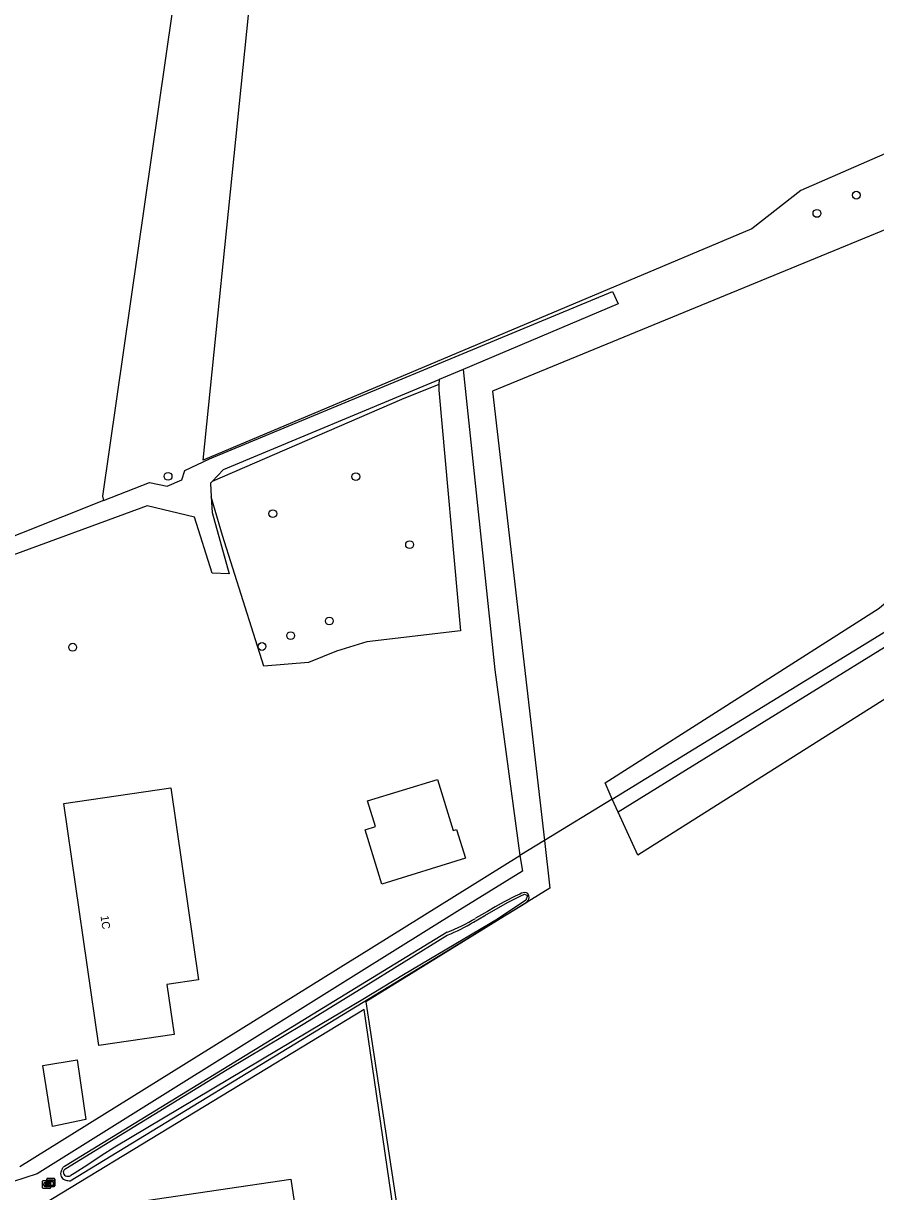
# Model space of a CAD drawing. Extents: x 162722 to 165099, y 384721 to 386283.
# Drawn here: x 164178.9 to 164285.4, y 385084.3 to 385230.3 of the extents above; entities that cross this region are included whole.
import ezdxf

# ---------------------------------------------------------------- set-up
doc = ezdxf.new("R2010")
doc.units = 0
for name, color, linetype in [('IMGEO_Boom', 7, 'Continuous'), ('IMGEO_Grasland_agrarisch', 7, 'Continuous'), ('IMGEO_Grasland_overig', 7, 'Continuous'), ('IMGEO_Groenvoorziening', 7, 'Continuous'), ('IMGEO_Kast', 7, 'Continuous'), ('IMGEO_Loofbos', 7, 'Continuous'), ('IMGEO_Pand', 7, 'Continuous'), ('IMGEO_Pand_nummerreeks', 7, 'Continuous'), ('IMGEO_Rioolput', 7, 'Continuous'), ('IMGEO_Waterloop', 7, 'Continuous')]:
    doc.layers.add(name, color=color, linetype=linetype)

msp = doc.modelspace()

# ---------------------------------------------------------------- linework, layer by layer
at = {"layer": 'IMGEO_Boom'}
for centre in [(164282.97, 385208.81), (164278.05, 385206.53), (164197, 385173.67), (164220.46, 385173.63), (164210.08, 385169.01), (164227.17, 385165.13), (164217.14, 385155.59), (164208.74, 385152.41), (164212.32, 385153.76), (164185.08, 385152.31)]:
    msp.add_circle(centre, 0.489, dxfattribs=at)
at = {"layer": 'IMGEO_Grasland_agrarisch'}
msp.add_lwpolyline([(164252.48, 385133.34), (164244.01, 385128.16)], dxfattribs=at)
at = {"layer": 'IMGEO_Grasland_overig'}
for points in [[(164340.77, 385221.28), (164343.9, 385222.64), (164341.32, 385235.52), (164343.58, 385278.11), (164335.24, 385279.06), (164332.81, 385234.21), (164276.04, 385209.41), (164269.93, 385204.62), (164201.37, 385175.67), (164210.46, 385264.87), (164255.72, 385265.96), (164258.91, 385289.28), (164301.34, 385288.31), (164341.47, 385287.14), (164341.48, 385289.48)], [(164340.77, 385221.28), (164336.68, 385219.5), (164334.56, 385224.22), (164237.51, 385184.33), (164244.01, 385128.16)], [(164252.48, 385133.34), (164251.58, 385135.35), (164285.82, 385157.18), (164294.31, 385164.54), (164346.7, 385197.08), (164338.62, 385215.04), (164340.88, 385216.06)], [(164233.88, 385187.02), (164237.83, 385149.49), (164240.96, 385126.27)], [(164230.83, 385185.14), (164230.84, 385184.42), (164233.54, 385154.37), (164221.83, 385152.99), (164218.02, 385151.84), (164214.54, 385150.39), (164208.97, 385149.93), (164203.78, 385166.27), (164202.39, 385171.09)], [(164230.83, 385185.14), (164226.17, 385183.27), (164202.51, 385173.04)], [(164230.87, 385185.76), (164230.83, 385185.14)], [(164244.01, 385128.16), (164244.69, 385122.21), (164221.69, 385107.99), (164230.18, 385052.07), (164300.52, 385079.04), (164292.21, 385149.4), (164255.66, 385126.31), (164253.22, 385131.71)], [(164244.01, 385128.16), (164240.96, 385126.27)], [(164240.96, 385126.27), (164241.27, 385124.33), (164233.44, 385119.49), (164220.83, 385111.6), (164180.65, 385086.48), (164177.57, 385085.49)], [(164240.93, 385121.47), (164240.35, 385121.18), (164238.99, 385120.48), (164238.22, 385120.07), (164237.84, 385119.85), (164236.9, 385119.3), (164235.4, 385118.43)], [(164242.07, 385121.24), (164241.95, 385121.54), (164241.79, 385121.63)], [(164221.36, 385107.95), (164241.68, 385120.36), (164241.85, 385120.5)], [(164231.87, 385116.69), (164221.05, 385110.07), (164184.27, 385087.56), (164184.07, 385087.43)], [(164184.76, 385085.64), (164221.36, 385107.95)], [(164229.04, 385055.46), (164221.49, 385107.05), (164179.29, 385081.39)], [(164183.63, 385086.15), (164183.71, 385086.04)]]:
    msp.add_lwpolyline(points, dxfattribs=at)
for centre, radius, start, end in [((164241.59, 385120.27), 1.37, 81.7747, 118.8821), ((164241.28, 385121.07), 0.807, 315.2978, 11.9062), ((164222.49, 385140.32), 25.42, 291.6617, 300.5441), ((164185.21, 385086.33), 1.64, 149.9616, 162.1799), ((164184.59, 385086.62), 0.969, 122.3471, 146.2382), ((164184.72, 385086.44), 1.15, 159.823, 174.3941), ((164185.02, 385086.54), 1.44, 179.4352, 195.586), ((164184.45, 385086.61), 0.93, 218.0278, 256.6584), ((164184.8, 385087.93), 2.3, 255.6812, 269.0302)]:
    msp.add_arc(centre, radius, start, end, dxfattribs=at)
at = {"layer": 'IMGEO_Groenvoorziening'}
msp.add_lwpolyline([(164178.48, 385087.43), (164219.79, 385113.12), (164220.53, 385113.58), (164240.96, 385126.27)], dxfattribs=at)
at = {"layer": 'IMGEO_Kast'}
for p, q in [((164181.86, 385085), (164181.86, 385085.84)), ((164181.86, 385085.84), (164181.86, 385085)), ((164181.93, 385085.93), (164182.77, 385085.93)), ((164182.77, 385085.93), (164181.93, 385085.93)), ((164182.86, 385085.85), (164182.86, 385085.01)), ((164182.86, 385085.01), (164182.86, 385085.85)), ((164182.78, 385084.93), (164181.94, 385084.93)), ((164181.94, 385084.93), (164182.78, 385084.93))]:
    msp.add_line(p, q, dxfattribs=at)
for points in [[(164182.05, 385085.72), (164182.65, 385085.72), (164182.65, 385085.63), (164182.05, 385085.63), (164182.05, 385085.72)], [(164182.05, 385085.54), (164182.65, 385085.54), (164182.65, 385085.05), (164182.05, 385085.05), (164182.05, 385085.54)]]:
    msp.add_lwpolyline(points, dxfattribs=at)
msp.add_circle((164182.13, 385085.39), 0.0377, dxfattribs=at)
for centre, start, end in [((164181.93, 385085.85), 92.4484, 184.2845), ((164181.93, 385085.85), 92.4484, 184.2845), ((164182.78, 385085.85), 2.4484, 94.2845), ((164182.78, 385085.85), 2.4484, 94.2845), ((164181.93, 385085.01), 182.4484, 274.2845), ((164181.93, 385085.01), 182.4484, 274.2845), ((164182.78, 385085.01), 272.4484, 4.2845), ((164182.78, 385085.01), 272.4484, 4.2845)]:
    msp.add_arc(centre, 0.0779, start, end, dxfattribs=at)
at = {"layer": 'IMGEO_Loofbos'}
msp.add_lwpolyline([(164249.34, 385270.02), (164249.26, 385269.41), (164202.97, 385269.71), (164200.14, 385250), (164188.82, 385171.2), (164188.95, 385170.65)], dxfattribs=at)
at = {"layer": 'IMGEO_Pand'}
for points in [[(164230.65, 385135.8), (164232.62, 385129.42), (164233.03, 385129.55), (164234.14, 385125.93), (164223.7, 385122.72), (164221.61, 385129.5), (164222.89, 385129.9), (164221.9, 385133.1), (164230.65, 385135.8)], [(164197.33, 385134.72), (164200.81, 385110.76), (164196.84, 385110.18), (164197.76, 385103.92), (164188.36, 385102.55), (164183.97, 385132.78), (164197.33, 385134.72)], [(164186.72, 385093.28), (164182.57, 385092.42), (164181.34, 385100.04), (164185.64, 385100.73), (164186.72, 385093.28)], [(164193.02, 385069.87), (164194.22, 385070.04), (164193.96, 385072.01), (164192.73, 385071.88), (164192.71, 385072), (164191.23, 385082.74), (164194.26, 385083.18), (164212.34, 385085.85)], [(164212.34, 385085.85), (164213.95, 385074.96), (164202.38, 385073.26), (164203.83, 385063.48), (164215.39, 385065.18), (164216.96, 385054.52), (164195.84, 385051.4), (164194.17, 385062.08), (164195.37, 385062.2), (164195.08, 385064.19), (164193.89, 385064.02)]]:
    msp.add_lwpolyline(points, dxfattribs=at)
at = {"layer": 'IMGEO_Rioolput'}
for p, q in [((164181.39, 385085.67), (164182.25, 385085.67)), ((164181.32, 385084.74), (164181.32, 385085.6)), ((164182.25, 385084.67), (164181.39, 385084.67)), ((164181.83, 385084.89), (164181.8, 385084.89)), ((164181.81, 385085.45), (164181.83, 385085.45)), ((164182.32, 385085.6), (164182.32, 385084.74))]:
    msp.add_line(p, q, dxfattribs=at)
for points in [[(164181.39, 385085.67), (164182.25, 385085.67)], [(164181.32, 385084.74), (164181.32, 385085.6)], [(164182.25, 385084.67), (164181.39, 385084.67)], [(164181.91, 385085.37), (164181.66, 385085.37), (164181.66, 385084.97)], [(164181.66, 385084.97), (164181.78, 385084.97), (164181.78, 385085.13), (164181.79, 385085.13)], [(164181.83, 385085.29), (164181.78, 385085.29), (164181.78, 385085.21)], [(164181.78, 385085.21), (164181.83, 385085.21)], [(164181.84, 385085.1), (164181.91, 385084.97), (164182.05, 385084.97), (164181.98, 385085.1)], [(164182.32, 385085.6), (164182.32, 385084.74)]]:
    msp.add_lwpolyline(points, dxfattribs=at)
for centre, radius, start, end in [((164181.4, 385085.59), 0.0765, 91.552, 178.448), ((164181.4, 385085.59), 0.0765, 91.552, 178.448), ((164182.24, 385085.59), 0.0765, 1.552, 88.448), ((164182.24, 385085.59), 0.0765, 1.552, 88.448), ((164181.4, 385084.75), 0.0765, 181.552, 268.448), ((164181.4, 385084.75), 0.0765, 181.552, 268.448), ((164181.79, 385085.08), 0.0533, 26.0293, 88.6989), ((164181.84, 385085.19), 0.0964, 77.0061, 93.1865), ((164181.82, 385085.4), 0.19, 274.7715, 282.9687), ((164181.85, 385085.25), 0.0378, 276.6634, 79.6772), ((164181.91, 385085.26), 0.109, 350.3612, 89.416), ((164181.91, 385085.26), 0.112, 277.5842, 350.9817), ((164181.89, 385085.04), 0.108, 29.5134, 73.7905), ((164182.24, 385084.75), 0.0765, 271.552, 358.448), ((164182.24, 385084.75), 0.0765, 271.552, 358.448)]:
    msp.add_arc(centre, radius, start, end, dxfattribs=at)
for centre, major_axis, ratio, start_param, end_param in [((164181.81, 385085.17), (-0.387, 0.002), 0.722429, 4.712389, 7.853982), ((164181.83, 385085.17), (-0.39, 0.002), 0.717154, 1.570796, 4.712389)]:
    msp.add_ellipse(centre, major_axis=major_axis, ratio=ratio, start_param=start_param, end_param=end_param, dxfattribs=at)
at = {"layer": 'IMGEO_Waterloop'}
for points in [[(164188.95, 385170.65), (164168.39, 385162.5), (164168.33, 385163.01), (164165.86, 385176.93), (164165.62, 385178.27), (164165.47, 385179.88), (164165.46, 385181.5), (164165.91, 385193.19), (164172.57, 385235.47)], [(164252.48, 385133.34), (164288.71, 385155.57), (164289.67, 385156.19), (164290.58, 385156.88), (164291.42, 385157.66), (164291.93, 385158.2), (164296.21, 385162.18), (164301.47, 385166.31), (164307.08, 385169.96), (164324.9, 385181.21), (164328.26, 385182.77), (164335.69, 385187.86), (164349.82, 385196.17), (164342.47, 385212.62), (164340.88, 385216.06)], [(164188.95, 385170.65), (164194.67, 385172.91), (164196.87, 385172.46), (164198.7, 385173.23), (164199.09, 385174.39), (164202.18, 385175.84), (164252.5, 385196.76), (164253.23, 385195.21), (164233.88, 385187.02)], [(164233.88, 385187.02), (164230.87, 385185.76)], [(164202.51, 385173.04), (164203.93, 385174.51), (164230.87, 385185.76)], [(164202.51, 385173.04), (164202.3, 385172.81), (164202.39, 385171.09)], [(164202.39, 385171.09), (164202.49, 385169.16), (164204.63, 385161.47), (164202.5, 385161.57), (164200.32, 385168.58), (164194.37, 385169.97), (164189.52, 385168.2), (164177.59, 385163.82), (164168.61, 385160.67), (164170.02, 385149.09), (164170.22, 385147.45), (164169.62, 385147.48)], [(164293.59, 385156.64), (164271.47, 385142.98), (164253.22, 385131.71)], [(164253.22, 385131.71), (164252.48, 385133.34)], [(164235.17, 385117.96), (164236.57, 385118.79), (164239.41, 385120.42), (164240.5, 385120.97), (164241.06, 385121.26), (164241.53, 385121.45), (164241.89, 385121.28), (164241.7, 385120.69), (164238.13, 385118.34), (164226.42, 385111.35), (164221.31, 385108.3), (164214.67, 385104.34), (164190.34, 385089.83), (164188.64, 385088.74), (164186.96, 385087.63), (164185.28, 385086.52), (164184.87, 385086.28)], [(164213.88, 385105.21), (164221.11, 385109.67), (164231.88, 385116.33)], [(164184.1, 385087.07), (164184.21, 385087.15), (164204.38, 385099.54), (164213.88, 385105.21)]]:
    msp.add_lwpolyline(points, dxfattribs=at)
for centre, radius, start, end in [((164222.75, 385138.93), 24.37, 292.0007, 300.6409), ((164184.39, 385086.68), 0.484, 126.3464, 174.416), ((164184.46, 385086.75), 0.55, 182.199, 241.2515), ((164184.52, 385086.93), 0.741, 243.7026, 297.9924)]:
    msp.add_arc(centre, radius, start, end, dxfattribs=at)

# ---------------------------------------------------------------- texts
at = {"layer": 'IMGEO_Pand_nummerreeks'}
msp.add_text('1C', height=1, rotation=278.2464, dxfattribs=at).set_placement((164188.56, 385118.71))

doc.saveas('drawing.dxf')
